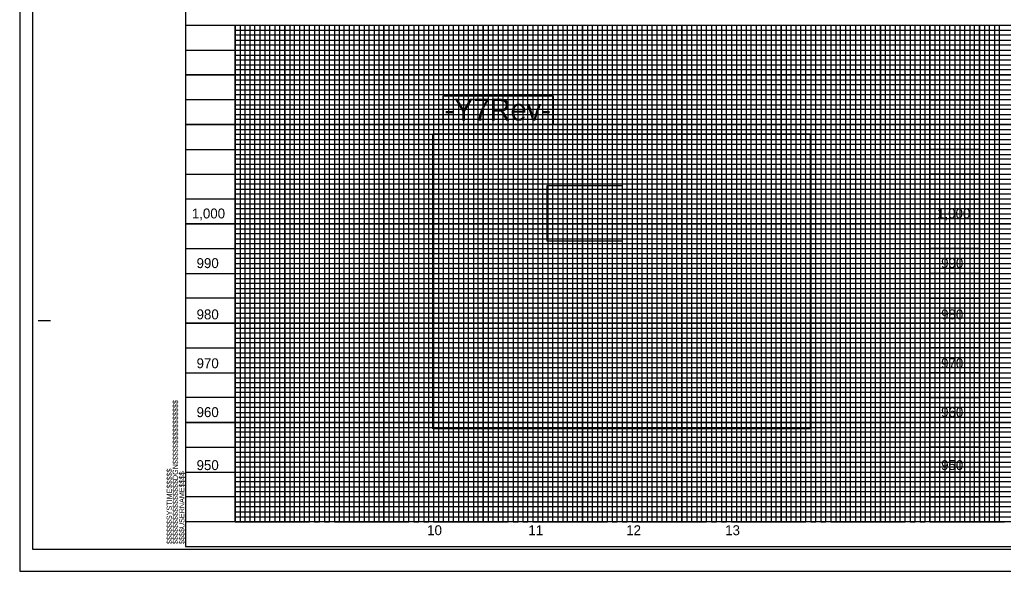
# Model space of a CAD drawing. Extents: x 1621288 to 1629363, y 896995 to 899414.
# Drawn here: x 1627302 to 1628293, y 896995 to 897550 of the extents above; entities that cross this region are included whole.
import ezdxf

# ---------------------------------------------------------------- set-up
doc = ezdxf.new("R2010")
doc.units = 0
for name, color, linetype in [('Exist Profile Cell', 7, 'Continuous'), ('Exist Structure Minor Pipes CMAP 112inx75in', 7, 'Continuous'), ('Exist Vertical Profile Horizontal Axis Label Major', 7, 'Continuous'), ('Exist XS Ground Line', 7, 'Continuous'), ('Prop Horizontal Alignment Curve and Spiral Data', 7, 'Continuous'), ('Prop Terminator CELL', 7, 'Continuous'), ('Prop Vertical Profile Curve Label', 7, 'Continuous'), ('Prop Vertical Profile Grade', 7, 'Continuous'), ('Prop VPI Label', 7, 'Continuous'), ('Sheet Layout Plan Border', 7, 'Continuous'), ('Sheet Layout Profile Border', 7, 'Continuous'), ('Sheet Layout Profile Border Port 2', 7, 'Continuous')]:
    doc.layers.add(name, color=color, linetype=linetype)

msp = doc.modelspace()

# ---------------------------------------------------------------- linework, layer by layer
at = {"layer": 'Exist Profile Cell'}
for p, q in [((1627519.38, 897539.66), (1628919.38, 897539.66)), ((1628919.38, 897534.66), (1627519.38, 897534.66)), ((1627519.38, 897529.66), (1628919.38, 897529.66)), ((1628919.38, 897524.66), (1627519.38, 897524.66)), ((1627519.38, 897514.66), (1628919.38, 897514.66)), ((1628919.38, 897509.66), (1627519.38, 897509.66)), ((1627519.38, 897504.66), (1628919.38, 897504.66)), ((1628919.38, 897499.66), (1627519.38, 897499.66)), ((1627519.38, 897489.66), (1628919.38, 897489.66)), ((1628919.38, 897484.66), (1627519.38, 897484.66)), ((1627519.38, 897479.66), (1628919.38, 897479.66)), ((1628919.38, 897474.66), (1627519.38, 897474.66)), ((1627519.38, 897464.66), (1628919.38, 897464.66)), ((1628919.38, 897459.66), (1627519.38, 897459.66)), ((1627519.38, 897454.66), (1628919.38, 897454.66)), ((1628919.38, 897449.66), (1627519.38, 897449.66)), ((1627519.38, 897439.66), (1628919.38, 897439.66)), ((1628919.38, 897434.66), (1627519.38, 897434.66)), ((1627519.38, 897429.66), (1628919.38, 897429.66)), ((1628919.38, 897424.66), (1627519.38, 897424.66)), ((1627519.38, 897414.66), (1628919.38, 897414.66)), ((1628919.38, 897409.66), (1627519.38, 897409.66)), ((1627519.38, 897404.66), (1628919.38, 897404.66)), ((1628919.38, 897399.66), (1627519.38, 897399.66)), ((1627519.38, 897389.66), (1628919.38, 897389.66)), ((1628919.38, 897384.66), (1627519.38, 897384.66)), ((1627519.38, 897379.66), (1628919.38, 897379.66)), ((1628919.38, 897374.66), (1627519.38, 897374.66)), ((1627519.38, 897364.66), (1628919.38, 897364.66)), ((1628919.38, 897359.66), (1627519.38, 897359.66)), ((1627519.38, 897354.66), (1628919.38, 897354.66)), ((1628919.38, 897349.66), (1627519.38, 897349.81)), ((1627519.38, 897339.66), (1628919.38, 897339.66)), ((1628919.38, 897334.66), (1627519.38, 897334.66)), ((1627519.38, 897329.66), (1628919.38, 897329.66)), ((1628919.38, 897324.66), (1627519.38, 897324.66)), ((1627519.38, 897314.66), (1628919.38, 897314.66)), ((1628919.38, 897309.66), (1627519.38, 897309.66)), ((1627519.38, 897304.66), (1628919.38, 897304.66)), ((1628919.38, 897299.66), (1627519.38, 897299.66)), ((1627519.38, 897289.66), (1628919.38, 897289.66)), ((1628919.38, 897284.66), (1627519.38, 897284.66)), ((1627519.38, 897279.66), (1628919.38, 897279.66)), ((1628919.38, 897274.66), (1627519.38, 897274.66)), ((1627519.38, 897264.66), (1628919.38, 897264.66)), ((1628919.38, 897259.66), (1627519.38, 897259.66)), ((1627519.38, 897254.66), (1628919.38, 897254.66)), ((1628919.38, 897249.66), (1627519.38, 897249.66)), ((1627519.38, 897239.66), (1628919.38, 897239.66)), ((1628919.38, 897234.66), (1627519.38, 897234.66)), ((1627519.38, 897229.66), (1628919.38, 897229.66)), ((1628919.38, 897224.66), (1627519.38, 897224.66)), ((1627519.38, 897214.66), (1628919.38, 897214.66)), ((1628919.38, 897209.66), (1627519.38, 897209.66)), ((1627519.38, 897204.66), (1628919.38, 897204.66)), ((1628919.38, 897199.66), (1627519.38, 897199.66)), ((1627519.38, 897189.66), (1628919.38, 897189.66)), ((1628919.38, 897184.66), (1627519.38, 897184.66)), ((1627519.38, 897179.66), (1628919.38, 897179.66)), ((1628919.38, 897174.66), (1627519.38, 897174.66)), ((1627519.38, 897164.66), (1628919.38, 897164.66)), ((1628919.38, 897159.66), (1627519.38, 897159.66)), ((1627519.38, 897154.66), (1628919.38, 897154.66)), ((1628919.38, 897149.66), (1627519.38, 897149.66)), ((1627519.38, 897139.66), (1628919.38, 897139.66)), ((1628919.38, 897134.66), (1627519.38, 897134.66)), ((1627519.38, 897129.66), (1628919.38, 897129.66)), ((1628919.38, 897124.66), (1627519.38, 897124.66)), ((1627519.38, 897114.66), (1628919.38, 897114.66)), ((1628919.38, 897109.66), (1627519.38, 897109.66)), ((1627519.38, 897104.66), (1628919.38, 897104.66)), ((1628919.38, 897099.66), (1627519.38, 897099.66)), ((1627519.38, 897089.66), (1628919.38, 897089.66)), ((1628919.38, 897084.66), (1627519.38, 897084.66)), ((1627519.38, 897079.66), (1628919.38, 897079.66)), ((1628919.38, 897074.66), (1627519.38, 897074.66)), ((1627519.38, 897064.66), (1628919.38, 897064.66)), ((1628919.38, 897059.66), (1627519.38, 897059.66)), ((1627519.38, 897054.66), (1628919.38, 897054.66)), ((1627519.38, 897049.66), (1628919.38, 897049.66))]:
    msp.add_line(p, q, dxfattribs=at)
for points in [[(1627519.38, 897544.66), (1627524.38, 897544.66), (1627524.38, 897044.66), (1627529.38, 897044.66), (1627529.38, 897544.66), (1627534.38, 897544.66), (1627534.38, 897044.66), (1627539.38, 897044.66), (1627539.38, 897544.66), (1627549.38, 897544.66), (1627549.38, 897044.66), (1627554.38, 897044.66), (1627554.38, 897544.66), (1627559.38, 897544.66), (1627559.38, 897044.66), (1627564.38, 897044.66), (1627574.38, 897044.66), (1627579.38, 897044.66), (1627579.38, 897544.66), (1627584.38, 897544.66), (1627584.38, 897044.66), (1627589.38, 897044.66), (1627589.38, 897544.66), (1627599.38, 897544.66), (1627599.38, 897044.66), (1627604.38, 897044.66), (1627604.38, 897544.66), (1627609.38, 897544.66), (1627609.38, 897044.66), (1627614.38, 897044.66), (1627614.38, 897544.66), (1627624.38, 897544.66), (1627624.38, 897044.66), (1627629.38, 897044.66), (1627629.38, 897544.66), (1627634.38, 897544.66), (1627634.38, 897044.66), (1627639.38, 897044.66), (1627639.38, 897544.66), (1627649.38, 897544.66), (1627649.38, 897044.66), (1627654.38, 897044.66), (1627654.38, 897544.66), (1627659.38, 897544.66), (1627659.38, 897044.66), (1627664.38, 897044.66), (1627664.38, 897544.66), (1627674.38, 897544.66), (1627674.38, 897044.66), (1627679.38, 897044.66), (1627679.38, 897544.66), (1627684.38, 897544.66), (1627684.38, 897044.66), (1627689.38, 897044.66), (1627689.38, 897544.66), (1627699.38, 897544.66), (1627699.38, 897044.66), (1627704.38, 897044.66), (1627704.38, 897544.66), (1627709.38, 897544.66), (1627709.38, 897044.66), (1627714.38, 897044.66), (1627714.38, 897544.66), (1627724.38, 897544.66), (1627724.38, 897044.66), (1627729.38, 897044.66), (1627729.38, 897544.66), (1627734.38, 897544.66), (1627734.38, 897044.66)], [(1627564.38, 897044.66), (1627564.38, 897544.66), (1627574.38, 897544.66), (1627574.38, 897044.66)], [(1627734.38, 897044.66), (1627739.38, 897044.66), (1627739.38, 897544.66), (1627749.38, 897544.66), (1627749.38, 897044.66), (1627754.38, 897044.66), (1627754.38, 897544.66), (1627759.38, 897544.66), (1627759.38, 897044.66), (1627764.38, 897044.66), (1627764.38, 897544.66), (1627774.38, 897544.66), (1627774.38, 897044.66), (1627779.38, 897044.66), (1627779.38, 897544.66), (1627784.38, 897544.66), (1627784.38, 897044.66), (1627789.38, 897044.66), (1627789.38, 897544.66), (1627799.38, 897544.66), (1627799.38, 897044.66), (1627804.38, 897044.66), (1627804.38, 897544.66), (1627809.38, 897544.66), (1627809.38, 897044.66), (1627814.38, 897044.66), (1627814.38, 897544.66), (1627824.38, 897544.66), (1627824.38, 897044.66), (1627829.38, 897044.66), (1627829.38, 897544.66), (1627834.38, 897544.66), (1627834.38, 897044.66), (1627839.38, 897044.66), (1627839.38, 897544.66), (1627849.38, 897544.66), (1627849.38, 897044.66), (1627854.38, 897044.66), (1627854.38, 897544.66), (1627859.38, 897544.66), (1627859.38, 897044.66), (1627864.38, 897044.66), (1627864.38, 897544.66), (1627874.38, 897544.66), (1627874.38, 897044.66), (1627879.38, 897044.66), (1627879.38, 897544.66), (1627884.38, 897544.66), (1627884.38, 897044.66), (1627889.38, 897044.66), (1627889.38, 897544.66), (1627899.38, 897544.66), (1627899.38, 897044.66), (1627904.38, 897044.66), (1627904.38, 897544.66), (1627909.38, 897544.66), (1627909.38, 897044.66), (1627914.38, 897044.66), (1627914.38, 897544.66), (1627924.38, 897544.66), (1627924.38, 897044.66), (1627929.38, 897044.66), (1627929.38, 897544.66), (1627934.38, 897544.66), (1627934.38, 897044.66), (1627939.38, 897044.66), (1627939.38, 897544.66), (1627949.38, 897544.66), (1627949.38, 897044.66), (1627954.38, 897044.66), (1627954.38, 897544.66), (1627959.38, 897544.66), (1627959.38, 897044.66), (1627964.38, 897044.66), (1627964.38, 897544.66), (1627974.38, 897544.66), (1627974.38, 897044.66), (1627979.38, 897044.66), (1627979.38, 897544.66), (1627984.38, 897544.66), (1627984.38, 897044.66), (1627989.38, 897044.66), (1627989.38, 897544.66), (1627999.38, 897544.66), (1627999.38, 897044.66), (1628004.38, 897044.66), (1628004.38, 897544.66), (1628009.38, 897544.66), (1628009.38, 897044.66), (1628014.38, 897044.66), (1628014.38, 897544.66), (1628024.38, 897544.66), (1628024.38, 897044.66), (1628029.38, 897044.66), (1628029.38, 897544.66), (1628034.38, 897544.66), (1628034.38, 897044.66), (1628039.38, 897044.66), (1628039.38, 897544.66), (1628049.38, 897544.66)], [(1628049.38, 897544.66), (1628049.38, 897044.66), (1628054.38, 897044.66), (1628054.38, 897544.66), (1628059.38, 897544.66), (1628059.38, 897044.66), (1628064.38, 897044.66), (1628064.38, 897544.66), (1628074.38, 897544.66), (1628074.38, 897044.66), (1628079.38, 897044.66), (1628079.38, 897544.66), (1628084.38, 897544.66), (1628084.38, 897044.66), (1628089.38, 897044.66), (1628089.38, 897544.66), (1628099.38, 897544.66), (1628099.38, 897044.66), (1628104.38, 897044.66), (1628104.38, 897544.66), (1628109.38, 897544.66), (1628109.38, 897044.66), (1628114.38, 897044.66), (1628114.38, 897544.66), (1628124.38, 897544.66), (1628124.38, 897044.66), (1628129.38, 897044.66), (1628129.38, 897544.66), (1628134.38, 897544.66), (1628134.38, 897044.66), (1628139.38, 897044.66), (1628139.38, 897544.66), (1628149.38, 897544.66), (1628149.38, 897044.66), (1628154.38, 897044.66), (1628154.38, 897544.66), (1628159.38, 897544.66), (1628159.38, 897044.66), (1628164.38, 897044.66), (1628164.38, 897544.66), (1628174.38, 897544.66), (1628174.38, 897044.66), (1628174.38, 897044.66), (1628179.38, 897044.66), (1628179.38, 897544.66), (1628184.38, 897544.66), (1628184.38, 897044.66), (1628189.38, 897044.66), (1628189.38, 897544.66), (1628199.38, 897544.66), (1628199.38, 897044.66), (1628204.38, 897044.66), (1628204.38, 897544.66), (1628209.38, 897544.66), (1628209.38, 897044.66), (1628214.38, 897044.66), (1628214.38, 897544.66), (1628224.38, 897544.66), (1628224.38, 897044.66), (1628229.38, 897044.66), (1628229.38, 897544.66), (1628234.38, 897544.66), (1628234.38, 897044.66), (1628239.38, 897044.66), (1628239.38, 897544.66), (1628249.38, 897544.66), (1628249.38, 897044.66), (1628254.38, 897044.66), (1628254.38, 897544.66), (1628259.38, 897544.66), (1628259.38, 897044.66), (1628264.38, 897044.66), (1628264.38, 897544.66), (1628274.38, 897544.66), (1628274.38, 897044.66), (1628279.38, 897044.66), (1628279.38, 897544.66), (1628284.38, 897544.66), (1628284.38, 897044.66), (1628289.38, 897044.66), (1628289.38, 897544.66), (1628299.38, 897544.66)]]:
    msp.add_lwpolyline(points, dxfattribs=at)
at = {"layer": 'Exist Structure Minor Pipes CMAP 112inx75in'}
msp.add_lwpolyline([(1627718.67, 897435.15), (1628098.55, 897435.15), (1628098.55, 897138.23), (1627718.67, 897138.23)], close=True, dxfattribs=at)
at = {"layer": 'Exist Vertical Profile Horizontal Axis Label Major'}
for points in [[(1628219.38, 897544.66), (1628269.38, 897544.66), (1628269.38, 897519.66), (1628219.38, 897519.66)], [(1628219.38, 897519.66), (1628269.38, 897519.66), (1628269.38, 897494.66), (1628219.38, 897494.66)], [(1628219.38, 897494.66), (1628269.38, 897494.66), (1628269.38, 897469.66), (1628219.38, 897469.66)], [(1627728.82, 897473.64), (1627839.95, 897473.64), (1627839.95, 897444.66), (1627728.82, 897444.66)], [(1628219.38, 897469.66), (1628269.38, 897469.66), (1628269.38, 897444.66), (1628219.38, 897444.66)], [(1628219.38, 897444.66), (1628269.38, 897444.66), (1628269.38, 897419.66), (1628219.38, 897419.66)], [(1628219.38, 897419.66), (1628269.38, 897419.66), (1628269.38, 897394.66), (1628219.38, 897394.66)], [(1628219.38, 897394.66), (1628269.38, 897394.66), (1628269.38, 897369.66), (1628219.38, 897369.66)], [(1627833.68, 897383.38), (1627909.18, 897383.38), (1627909.18, 897327.07), (1627833.68, 897327.07)], [(1628219.38, 897369.66), (1628269.38, 897369.66), (1628269.38, 897344.66), (1628219.38, 897344.66)], [(1628219.38, 897344.66), (1628269.38, 897344.66), (1628269.38, 897319.66), (1628219.38, 897319.66)], [(1628219.38, 897319.66), (1628269.38, 897319.66), (1628269.38, 897294.66), (1628219.38, 897294.66)], [(1628219.38, 897294.66), (1628269.38, 897294.66), (1628269.38, 897269.66), (1628219.38, 897269.66)], [(1628219.38, 897269.66), (1628269.38, 897269.66), (1628269.38, 897244.66), (1628219.38, 897244.66)], [(1628219.38, 897244.66), (1628269.38, 897244.66), (1628269.38, 897219.66), (1628219.38, 897219.66)], [(1628219.38, 897219.66), (1628269.38, 897219.66), (1628269.38, 897194.66), (1628219.38, 897194.66)], [(1628219.38, 897194.66), (1628269.38, 897194.66), (1628269.38, 897169.66), (1628219.38, 897169.66)], [(1628219.38, 897169.66), (1628269.38, 897169.66), (1628269.38, 897144.66), (1628219.38, 897144.66)], [(1628219.38, 897144.66), (1628269.38, 897144.66), (1628269.38, 897119.66), (1628219.38, 897119.66)], [(1628219.38, 897119.66), (1628269.38, 897119.66), (1628269.38, 897094.66), (1628219.38, 897094.66)], [(1628219.38, 897094.66), (1628269.38, 897094.66), (1628269.38, 897069.66), (1628219.38, 897069.66)], [(1628219.38, 897069.66), (1628269.38, 897069.66), (1628269.38, 897044.66), (1628219.38, 897044.66)]]:
    msp.add_lwpolyline(points, close=True, dxfattribs=at)
at = {"layer": 'Exist XS Ground Line'}
for p, q in [((1627469.38, 897544.66), (1628969.38, 897544.66)), ((1627320.88, 897247.16), (1627333.38, 897247.16)), ((1628969.38, 897044.66), (1627469.38, 897044.66)), ((1627469.38, 897019.66), (1628969.38, 897019.66)), ((1627469.38, 897019.66), (1627469.38, 897019.66)), ((1627469.38, 897019.66), (1627469.38, 897019.66)), ((1627469.38, 897019.66), (1627469.38, 897019.66)), ((1627469.38, 897019.66), (1627469.38, 897019.66)), ((1627469.38, 897019.66), (1627469.38, 897019.66)), ((1627469.38, 897019.66), (1627469.38, 897019.66)), ((1627469.38, 897019.66), (1627469.38, 897019.66))]:
    msp.add_line(p, q, dxfattribs=at)
msp.add_lwpolyline([(1628969.38, 898069.66), (1627469.38, 898069.66), (1627469.38, 897019.66), (1628969.38, 897019.66)], close=True, dxfattribs=at)
msp.add_lwpolyline([(1627506.88, 897019.66), (1627506.88, 897019.66)], dxfattribs=at)
at = {"layer": 'Prop Terminator CELL'}
msp.add_lwpolyline([(1627519.38, 897544.66), (1628919.38, 897544.66), (1628919.38, 897044.66), (1627519.38, 897044.66)], close=True, dxfattribs=at)
at = {"layer": 'Prop Vertical Profile Curve Label'}
msp.add_lwpolyline([(1627315.38, 897017.11), (1628981.88, 897017.11), (1628981.88, 898072.21), (1627315.38, 898072.21)], close=True, dxfattribs=at)
at = {"layer": 'Prop Vertical Profile Grade'}
for points in [[(1627494.38, 897544.66), (1627544.38, 897544.66), (1627544.38, 897044.66), (1627594.38, 897044.66), (1627594.38, 897544.66), (1627644.38, 897544.66), (1627644.38, 897044.66), (1627694.38, 897044.66), (1627694.38, 897544.66), (1627744.38, 897544.66), (1627744.38, 897044.66), (1627794.38, 897044.66), (1627794.38, 897544.66), (1627844.38, 897544.66), (1627844.38, 897044.66), (1627894.38, 897044.66), (1627894.38, 897544.66), (1627944.38, 897544.66), (1627944.38, 897044.66), (1627994.38, 897044.66), (1627994.38, 897544.66), (1628044.38, 897544.66), (1628044.38, 897044.66), (1628094.38, 897044.66), (1628094.38, 897044.66), (1628094.38, 897544.66), (1628144.38, 897544.66), (1628144.38, 897044.66), (1628194.38, 897044.66), (1628194.38, 897544.66), (1628244.38, 897544.66), (1628244.38, 897044.66), (1628294.38, 897044.66)], [(1627469.38, 897519.66), (1628969.38, 897519.66)], [(1628969.38, 897469.66), (1627469.38, 897469.66), (1627469.38, 897419.66), (1628969.38, 897419.66)], [(1628969.38, 897369.66), (1627469.38, 897369.66), (1627469.38, 897319.66), (1628969.38, 897319.66)], [(1628969.38, 897269.66), (1627469.38, 897269.66), (1627469.38, 897219.66), (1628969.38, 897219.66)], [(1628969.38, 897169.66), (1627469.38, 897169.66), (1627469.38, 897119.66), (1628969.38, 897119.66)], [(1628969.38, 897069.66), (1627469.38, 897069.66)]]:
    msp.add_lwpolyline(points, dxfattribs=at)
at = {"layer": 'Prop VPI Label'}
for p, q in [((1627969.38, 897544.66), (1628019.38, 897544.66)), ((1628069.38, 897544.66), (1628119.38, 897544.66)), ((1628169.38, 897544.66), (1628219.38, 897544.66)), ((1628269.38, 897544.66), (1628319.38, 897544.66)), ((1628219.38, 897519.66), (1628269.38, 897519.66)), ((1628219.38, 897494.66), (1628269.38, 897494.66)), ((1628219.38, 897469.66), (1628269.38, 897469.66)), ((1628219.38, 897444.66), (1628269.38, 897444.66)), ((1628219.38, 897419.66), (1628269.38, 897419.66)), ((1628219.38, 897394.66), (1628269.38, 897394.66)), ((1628219.38, 897369.66), (1628269.38, 897369.66)), ((1628219.38, 897344.66), (1628269.38, 897344.66)), ((1628219.38, 897319.66), (1628269.38, 897319.66)), ((1628219.38, 897294.66), (1628269.38, 897294.66)), ((1628219.38, 897269.66), (1628269.38, 897269.66)), ((1628219.38, 897244.66), (1628269.38, 897244.66)), ((1628219.38, 897219.66), (1628269.38, 897219.66)), ((1628219.38, 897194.66), (1628269.38, 897194.66)), ((1628219.38, 897169.66), (1628269.38, 897169.66)), ((1628219.38, 897144.66), (1628269.38, 897144.66)), ((1628219.38, 897119.66), (1628269.38, 897119.66)), ((1628219.38, 897094.66), (1628269.38, 897094.66)), ((1628219.38, 897069.66), (1628269.38, 897069.66)), ((1627469.38, 897044.66), (1627469.38, 897044.66))]:
    msp.add_line(p, q, dxfattribs=at)
for points in [[(1627519.38, 897544.66), (1627519.38, 897044.66), (1627569.38, 897044.66), (1627569.38, 897544.66), (1627619.38, 897544.66), (1627619.38, 897044.66), (1627669.38, 897044.66), (1627669.38, 897544.66), (1627719.38, 897544.66), (1627719.38, 897044.66), (1627769.38, 897044.66), (1627769.38, 897544.66), (1627819.38, 897544.66), (1627819.38, 897044.66), (1627869.38, 897044.66), (1627869.38, 897544.66), (1627919.38, 897544.66), (1627919.38, 897044.66), (1627969.38, 897044.66), (1627969.38, 897544.66), (1628019.38, 897544.66), (1628019.38, 897044.66), (1628069.38, 897044.66), (1628069.38, 897544.66), (1628119.38, 897544.66), (1628119.38, 897044.66), (1628169.38, 897044.66), (1628169.38, 897544.66), (1628219.38, 897544.66), (1628219.38, 897044.66), (1628269.38, 897044.66), (1628269.38, 897544.66), (1628319.38, 897544.66)], [(1628969.38, 897494.66), (1627469.38, 897494.66)], [(1628969.38, 897444.66), (1627469.38, 897444.66), (1627469.38, 897394.66), (1628969.38, 897394.66)], [(1628969.38, 897344.66), (1627469.38, 897344.66), (1627469.38, 897294.66), (1628969.38, 897294.66)], [(1628969.38, 897244.66), (1627469.38, 897244.66), (1627469.38, 897194.66), (1628969.38, 897194.66)], [(1628969.38, 897144.66), (1627469.38, 897144.66), (1627469.38, 897144.66), (1627469.38, 897094.66), (1628969.38, 897094.66)], [(1628969.38, 897044.66), (1627469.38, 897044.66)]]:
    msp.add_lwpolyline(points, dxfattribs=at)
at = {"layer": 'Sheet Layout Plan Border'}
msp.add_lwpolyline([(1627302.38, 896994.66), (1628986.38, 896994.66), (1628986.38, 898094.66), (1627302.38, 898094.66)], close=True, dxfattribs=at)
at = {"layer": 'Sheet Layout Profile Border'}
for p, q in [((1627302.38, 898094.66), (1627302.38, 896994.66)), ((1627302.38, 896994.66), (1628986.38, 896994.66))]:
    msp.add_line(p, q, dxfattribs=at)
at = {"layer": 'Sheet Layout Profile Border Port 2'}
for p, q in [((1627469.38, 897544.66), (1628969.27, 897544.66)), ((1627519.38, 897544.66), (1627519.38, 897044.66)), ((1627569.38, 897544.66), (1627569.38, 897044.66)), ((1627619.38, 897544.66), (1627619.38, 897044.66)), ((1627669.38, 897544.66), (1627669.38, 897044.66)), ((1627719.38, 897544.66), (1627719.38, 897044.66)), ((1627769.38, 897544.66), (1627769.38, 897044.66)), ((1627819.38, 897544.66), (1627819.38, 897044.66)), ((1627869.38, 897544.66), (1627869.38, 897044.66)), ((1627919.38, 897544.66), (1627919.38, 897044.66)), ((1627969.38, 897544.66), (1627969.38, 897044.66)), ((1628019.38, 897544.66), (1628019.38, 897044.66)), ((1628069.38, 897544.66), (1628069.38, 897044.66)), ((1628119.38, 897544.66), (1628119.38, 897044.66)), ((1628169.38, 897544.66), (1628169.38, 897044.66)), ((1628219.38, 897544.66), (1628219.38, 897044.66)), ((1628269.38, 897544.66), (1628269.38, 897044.66)), ((1627469.38, 897494.66), (1628969.27, 897494.66)), ((1627469.38, 897444.66), (1628969.27, 897444.66)), ((1627469.38, 897394.66), (1628969.27, 897394.66)), ((1627469.38, 897344.66), (1628969.27, 897344.66)), ((1627469.38, 897294.66), (1628969.27, 897294.66)), ((1627469.38, 897244.66), (1628969.27, 897244.66)), ((1627469.38, 897194.66), (1628969.27, 897194.66)), ((1627469.38, 897144.66), (1628969.27, 897144.66)), ((1627469.38, 897094.66), (1628969.27, 897094.66))]:
    msp.add_line(p, q, dxfattribs=at)

# ---------------------------------------------------------------- texts
at = {"layer": 'Exist XS Ground Line'}
for s, p in [('$$$$$$$$$$$$$$$$DGN$$$$$$$$$$$$$$$$', (1627461.74, 897022.04)), ('$$$$$$SYSTIME$$$$$', (1627455.69, 897022.04)), ('$$$$USERNAME$$$$', (1627468.32, 897022.05))]:
    msp.add_text(s, height=5.25, rotation=90, dxfattribs=at).set_placement(p)
at = {"layer": 'Prop Horizontal Alignment Curve and Spiral Data'}
for s, height, p in [('-Y7Rev-', 21.875, (1627730.19, 897448.72)), ('1,000', 10, (1627475.82, 897350.09)), ('1,000', 10, (1628226.54, 897350.09)), ('990', 10, (1627480.6, 897300.09)), ('990', 10, (1628230.6, 897300.09)), ('980', 10, (1627480.6, 897248.44)), ('980', 10, (1628230.6, 897248.44)), ('970', 10, (1627480.6, 897199.22)), ('970', 10, (1628230.6, 897199.22)), ('960', 10, (1627480.6, 897149.99)), ('960', 10, (1628230.6, 897149.99)), ('950', 10, (1627480.6, 897096.63)), ('950', 10, (1628230.6, 897096.63)), ('10', 10, (1627712.86, 897031.07)), ('11', 10, (1627814.83, 897031.07)), ('12', 10, (1627913.4, 897031.07)), ('13', 10, (1628013.07, 897031.07))]:
    msp.add_text(s, height=height, dxfattribs=at).set_placement(p)

doc.saveas('drawing.dxf')
